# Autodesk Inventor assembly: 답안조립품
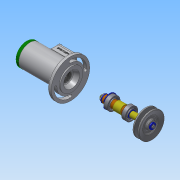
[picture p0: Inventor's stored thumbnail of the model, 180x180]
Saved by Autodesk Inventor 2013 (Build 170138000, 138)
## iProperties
Created: 2017-05
Part Number: 답안조립품
Document SubType Name: Assembly
Designer: Administrator
Author: Administrator
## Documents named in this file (20)
- C:\Users\Administrator\Desktop\470508V1023\답안조립품.iam
- C:\Users\Administrator\Desktop\470508V1023\V-벨트풀리.ipt
- C:\Users\Administrator\Desktop\470508V1023\너트 M10.ipt
- C:\Users\Administrator\Desktop\470508V1023\멈춤링 15 x 1.ipt
- C:\Users\Administrator\Desktop\470508V1023\멈춤링 35x1.6.ipt
- C:\Users\Administrator\Desktop\470508V1023\베어링 15 x 35 x 11.ipt
- C:\Users\Administrator\Desktop\470508V1023\본체.ipt
- C:\Users\Administrator\Desktop\470508V1023\볼트 M4 x 10.ipt
- C:\Users\Administrator\Desktop\470508V1023\부시1.ipt
- C:\Users\Administrator\Desktop\470508V1023\부시2.ipt
- C:\Users\Administrator\Desktop\470508V1023\사이드 커버.ipt
- 사이드 커버.ipt
- C:\Users\Administrator\Desktop\470508V1023\십자볼트 M3 x 10.ipt
- C:\Users\Administrator\Desktop\470508V1023\오일 실 15 25 7.ipt
- C:\Users\Administrator\Desktop\470508V1023\와셔 3x6.ipt
- C:\Users\Administrator\Desktop\470508V1023\와셔 4x16.ipt
- C:\Users\Administrator\Desktop\470508V1023\와셔 10x21.ipt
- C:\Users\Administrator\Desktop\470508V1023\축.ipt
- C:\Users\Administrator\Desktop\470508V1023\키 4 x 4 x 18.ipt
- C:\Users\Administrator\Desktop\470508V1023\탑 커버.ipt
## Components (2 placed, 2 different names)
1. V-벨트풀리:1
2. ISO 4017 M4 x 10:1
